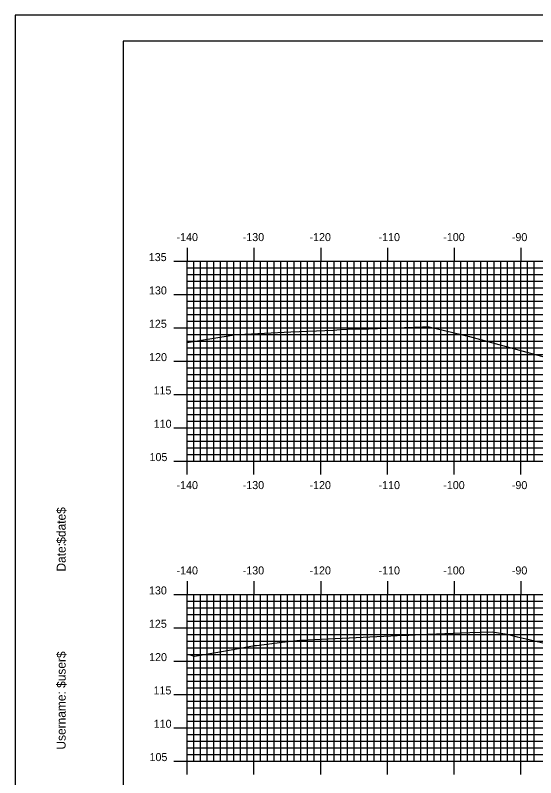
# Model space of a CAD drawing. Extents: x 854287 to 854631, y 366605 to 366825.
# Drawn here: x 854287.3 to 854365.3, y 366710.6 to 366824.9 of the extents above; entities that cross this region are included whole.
import ezdxf

# ---------------------------------------------------------------- set-up
doc = ezdxf.new("R2010")
doc.units = 0
for name, color, linetype in [('BORDER', 7, 'Continuous'), ('H_V ANNOTATION', 7, 'Continuous'), ('M_Roadway_Centerline', 7, 'Continuous'), ('MAJOR', 7, 'Continuous'), ('MINOR', 7, 'Continuous'), ('PLOT BOUNDARY', 7, 'Continuous'), ('S_Roadway_Centerline', 7, 'Continuous')]:
    doc.layers.add(name, color=color, linetype=linetype)

msp = doc.modelspace()

# ---------------------------------------------------------------- linework, layer by layer
at = {"layer": 'BORDER'}
msp.add_lwpolyline([(854303.44, 366611.06), (854623.44, 366611.06), (854623.44, 366821.06), (854303.44, 366821.06)], close=True, dxfattribs=at)
at = {"layer": 'MAJOR'}
for p, q in [((854313.04, 366790.06), (854313.04, 366788.06)), ((854323.04, 366790.06), (854323.04, 366788.06)), ((854333.04, 366790.06), (854333.04, 366788.06)), ((854343.04, 366790.06), (854343.04, 366788.06)), ((854353.04, 366790.06), (854353.04, 366788.06)), ((854363.04, 366790.06), (854363.04, 366788.06)), ((854311.04, 366788.06), (854313.04, 366788.06)), ((854313.04, 366788.06), (854593.04, 366788.06)), ((854313.04, 366758.06), (854313.04, 366788.06)), ((854313.04, 366758.06), (854313.04, 366788.06)), ((854313.04, 366788.06), (854593.04, 366788.06)), ((854323.04, 366758.06), (854323.04, 366788.06)), ((854333.04, 366758.06), (854333.04, 366788.06)), ((854343.04, 366758.06), (854343.04, 366788.06)), ((854353.04, 366758.06), (854353.04, 366788.06)), ((854363.04, 366758.06), (854363.04, 366788.06)), ((854311.04, 366783.06), (854313.04, 366783.06)), ((854313.04, 366783.06), (854593.04, 366783.06)), ((854311.04, 366778.06), (854313.04, 366778.06)), ((854313.04, 366778.06), (854593.04, 366778.06)), ((854311.04, 366773.06), (854313.04, 366773.06)), ((854313.04, 366773.06), (854593.04, 366773.06)), ((854311.04, 366768.06), (854313.04, 366768.06)), ((854313.04, 366768.06), (854593.04, 366768.06)), ((854311.04, 366763.06), (854313.04, 366763.06)), ((854313.04, 366763.06), (854593.04, 366763.06)), ((854311.04, 366758.06), (854313.04, 366758.06)), ((854313.04, 366758.06), (854593.04, 366758.06)), ((854313.04, 366758.06), (854593.04, 366758.06)), ((854313.04, 366756.05), (854313.04, 366758.06)), ((854323.04, 366756.05), (854323.04, 366758.06)), ((854333.04, 366756.05), (854333.04, 366758.06)), ((854343.04, 366756.05), (854343.04, 366758.06)), ((854353.04, 366756.05), (854353.04, 366758.06)), ((854363.04, 366756.05), (854363.04, 366758.06)), ((854313.04, 366740.06), (854313.04, 366738.06)), ((854323.04, 366740.06), (854323.04, 366738.06)), ((854333.04, 366740.06), (854333.04, 366738.06)), ((854343.04, 366740.06), (854343.04, 366738.06)), ((854353.04, 366740.06), (854353.04, 366738.06)), ((854363.04, 366740.06), (854363.04, 366738.06)), ((854311.04, 366738.06), (854313.04, 366738.06)), ((854313.04, 366738.06), (854593.04, 366738.06)), ((854313.04, 366713.06), (854313.04, 366738.06)), ((854313.04, 366713.06), (854313.04, 366738.06)), ((854313.04, 366738.06), (854593.04, 366738.06)), ((854323.04, 366713.06), (854323.04, 366738.06)), ((854333.04, 366713.06), (854333.04, 366738.06)), ((854343.04, 366713.06), (854343.04, 366738.06)), ((854353.04, 366713.06), (854353.04, 366738.06)), ((854363.04, 366713.06), (854363.04, 366738.06)), ((854311.04, 366733.06), (854313.04, 366733.06)), ((854313.04, 366733.06), (854593.04, 366733.06)), ((854311.04, 366728.06), (854313.04, 366728.06)), ((854313.04, 366728.06), (854593.04, 366728.06)), ((854311.04, 366723.06), (854313.04, 366723.06)), ((854313.04, 366723.06), (854593.04, 366723.06)), ((854311.04, 366718.06), (854313.04, 366718.06)), ((854313.04, 366718.06), (854593.04, 366718.06)), ((854311.04, 366713.06), (854313.04, 366713.06)), ((854313.04, 366713.06), (854593.04, 366713.06)), ((854313.04, 366713.06), (854593.04, 366713.06)), ((854313.04, 366711.05), (854313.04, 366713.06)), ((854323.04, 366711.05), (854323.04, 366713.06)), ((854333.04, 366711.05), (854333.04, 366713.06)), ((854343.04, 366711.05), (854343.04, 366713.06)), ((854353.04, 366711.05), (854353.04, 366713.06)), ((854363.04, 366711.05), (854363.04, 366713.06))]:
    msp.add_line(p, q, dxfattribs=at)
at = {"layer": 'MINOR'}
for p, q in [((854314.04, 366758.06), (854314.04, 366788.06)), ((854315.04, 366758.06), (854315.04, 366788.06)), ((854316.04, 366758.06), (854316.04, 366788.06)), ((854317.04, 366758.06), (854317.04, 366788.06)), ((854318.04, 366758.06), (854318.04, 366788.06)), ((854319.04, 366758.06), (854319.04, 366788.06)), ((854320.04, 366758.06), (854320.04, 366788.06)), ((854321.04, 366758.06), (854321.04, 366788.06)), ((854322.04, 366758.06), (854322.04, 366788.06)), ((854324.04, 366758.06), (854324.04, 366788.06)), ((854325.04, 366758.06), (854325.04, 366788.06)), ((854326.04, 366758.06), (854326.04, 366788.06)), ((854327.04, 366758.06), (854327.04, 366788.06)), ((854328.04, 366758.06), (854328.04, 366788.06)), ((854329.04, 366758.06), (854329.04, 366788.06)), ((854330.04, 366758.06), (854330.04, 366788.06)), ((854331.04, 366758.06), (854331.04, 366788.06)), ((854332.04, 366758.06), (854332.04, 366788.06)), ((854334.04, 366758.06), (854334.04, 366788.06)), ((854335.04, 366758.06), (854335.04, 366788.06)), ((854336.04, 366758.06), (854336.04, 366788.06)), ((854337.04, 366758.06), (854337.04, 366788.06)), ((854338.04, 366758.06), (854338.04, 366788.06)), ((854339.04, 366758.06), (854339.04, 366788.06)), ((854340.04, 366758.06), (854340.04, 366788.06)), ((854341.04, 366758.06), (854341.04, 366788.06)), ((854342.04, 366758.06), (854342.04, 366788.06)), ((854344.04, 366758.06), (854344.04, 366788.06)), ((854345.04, 366758.06), (854345.04, 366788.06)), ((854346.04, 366758.06), (854346.04, 366788.06)), ((854347.04, 366758.06), (854347.04, 366788.06)), ((854348.04, 366758.06), (854348.04, 366788.06)), ((854349.04, 366758.06), (854349.04, 366788.06)), ((854350.04, 366758.06), (854350.04, 366788.06)), ((854351.04, 366758.06), (854351.04, 366788.06)), ((854352.04, 366758.06), (854352.04, 366788.06)), ((854354.04, 366758.06), (854354.04, 366788.06)), ((854355.04, 366758.06), (854355.04, 366788.06)), ((854356.04, 366758.06), (854356.04, 366788.06)), ((854357.04, 366758.06), (854357.04, 366788.06)), ((854358.04, 366758.06), (854358.04, 366788.06)), ((854359.04, 366758.06), (854359.04, 366788.06)), ((854360.04, 366758.06), (854360.04, 366788.06)), ((854361.04, 366758.06), (854361.04, 366788.06)), ((854362.04, 366758.06), (854362.04, 366788.06)), ((854364.04, 366758.06), (854364.04, 366788.06)), ((854365.04, 366758.06), (854365.04, 366788.06)), ((854313.04, 366787.06), (854593.04, 366787.06)), ((854313.04, 366787.06), (854315.05, 366787.06)), ((854313.04, 366786.06), (854593.04, 366786.06)), ((854313.04, 366786.06), (854315.05, 366786.06)), ((854313.04, 366785.06), (854593.04, 366785.06)), ((854313.04, 366785.06), (854315.05, 366785.06)), ((854313.04, 366784.06), (854593.04, 366784.06)), ((854313.04, 366784.06), (854315.05, 366784.06)), ((854313.04, 366782.06), (854593.04, 366782.06)), ((854313.04, 366782.06), (854315.05, 366782.06)), ((854313.04, 366781.06), (854593.04, 366781.06)), ((854313.04, 366781.06), (854315.05, 366781.06)), ((854313.04, 366780.06), (854593.04, 366780.06)), ((854313.04, 366780.06), (854315.05, 366780.06)), ((854313.04, 366779.06), (854593.04, 366779.06)), ((854313.04, 366779.06), (854315.05, 366779.06)), ((854313.04, 366777.06), (854593.04, 366777.06)), ((854313.04, 366777.06), (854315.05, 366777.06)), ((854313.04, 366776.06), (854593.04, 366776.06)), ((854313.04, 366776.06), (854315.05, 366776.06)), ((854313.04, 366775.06), (854593.04, 366775.06)), ((854313.04, 366775.06), (854315.05, 366775.06)), ((854313.04, 366774.06), (854593.04, 366774.06)), ((854313.04, 366774.06), (854315.05, 366774.06)), ((854313.04, 366772.06), (854593.04, 366772.06)), ((854313.04, 366772.06), (854315.05, 366772.06)), ((854313.04, 366771.06), (854593.04, 366771.06)), ((854313.04, 366771.06), (854315.05, 366771.06)), ((854313.04, 366770.06), (854593.04, 366770.06)), ((854313.04, 366770.06), (854315.05, 366770.06)), ((854313.04, 366769.06), (854593.04, 366769.06)), ((854313.04, 366769.06), (854315.05, 366769.06)), ((854313.04, 366767.06), (854593.04, 366767.06)), ((854313.04, 366767.06), (854315.05, 366767.06)), ((854313.04, 366766.06), (854593.04, 366766.06)), ((854313.04, 366766.06), (854315.05, 366766.06)), ((854313.04, 366765.06), (854593.04, 366765.06)), ((854313.04, 366765.06), (854315.05, 366765.06)), ((854313.04, 366764.06), (854593.04, 366764.06)), ((854313.04, 366764.06), (854315.05, 366764.06)), ((854313.04, 366762.06), (854593.04, 366762.06)), ((854313.04, 366762.06), (854315.05, 366762.06)), ((854313.04, 366761.06), (854593.04, 366761.06)), ((854313.04, 366761.06), (854315.05, 366761.06)), ((854313.04, 366760.06), (854593.04, 366760.06)), ((854313.04, 366760.06), (854315.05, 366760.06)), ((854313.04, 366759.06), (854593.04, 366759.06)), ((854313.04, 366759.06), (854315.05, 366759.06)), ((854313.04, 366737.06), (854593.04, 366737.06)), ((854313.04, 366737.06), (854315.05, 366737.06)), ((854314.04, 366713.06), (854314.04, 366738.06)), ((854315.04, 366713.06), (854315.04, 366738.06)), ((854316.04, 366713.06), (854316.04, 366738.06)), ((854317.04, 366713.06), (854317.04, 366738.06)), ((854318.04, 366713.06), (854318.04, 366738.06)), ((854319.04, 366713.06), (854319.04, 366738.06)), ((854320.04, 366713.06), (854320.04, 366738.06)), ((854321.04, 366713.06), (854321.04, 366738.06)), ((854322.04, 366713.06), (854322.04, 366738.06)), ((854324.04, 366713.06), (854324.04, 366738.06)), ((854325.04, 366713.06), (854325.04, 366738.06)), ((854326.04, 366713.06), (854326.04, 366738.06)), ((854327.04, 366713.06), (854327.04, 366738.06)), ((854328.04, 366713.06), (854328.04, 366738.06)), ((854329.04, 366713.06), (854329.04, 366738.06)), ((854330.04, 366713.06), (854330.04, 366738.06)), ((854331.04, 366713.06), (854331.04, 366738.06)), ((854332.04, 366713.06), (854332.04, 366738.06)), ((854334.04, 366713.06), (854334.04, 366738.06)), ((854335.04, 366713.06), (854335.04, 366738.06)), ((854336.04, 366713.06), (854336.04, 366738.06)), ((854337.04, 366713.06), (854337.04, 366738.06)), ((854338.04, 366713.06), (854338.04, 366738.06)), ((854339.04, 366713.06), (854339.04, 366738.06)), ((854340.04, 366713.06), (854340.04, 366738.06)), ((854341.04, 366713.06), (854341.04, 366738.06)), ((854342.04, 366713.06), (854342.04, 366738.06)), ((854344.04, 366713.06), (854344.04, 366738.06)), ((854345.04, 366713.06), (854345.04, 366738.06)), ((854346.04, 366713.06), (854346.04, 366738.06)), ((854347.04, 366713.06), (854347.04, 366738.06)), ((854348.04, 366713.06), (854348.04, 366738.06)), ((854349.04, 366713.06), (854349.04, 366738.06)), ((854350.04, 366713.06), (854350.04, 366738.06)), ((854351.04, 366713.06), (854351.04, 366738.06)), ((854352.04, 366713.06), (854352.04, 366738.06)), ((854354.04, 366713.06), (854354.04, 366738.06)), ((854355.04, 366713.06), (854355.04, 366738.06)), ((854356.04, 366713.06), (854356.04, 366738.06)), ((854357.04, 366713.06), (854357.04, 366738.06)), ((854358.04, 366713.06), (854358.04, 366738.06)), ((854359.04, 366713.06), (854359.04, 366738.06)), ((854360.04, 366713.06), (854360.04, 366738.06)), ((854361.04, 366713.06), (854361.04, 366738.06)), ((854362.04, 366713.06), (854362.04, 366738.06)), ((854364.04, 366713.06), (854364.04, 366738.06)), ((854365.04, 366713.06), (854365.04, 366738.06)), ((854313.04, 366736.06), (854593.04, 366736.06)), ((854313.04, 366736.06), (854315.05, 366736.06)), ((854313.04, 366735.06), (854593.04, 366735.06)), ((854313.04, 366735.06), (854315.05, 366735.06)), ((854313.04, 366734.06), (854593.04, 366734.06)), ((854313.04, 366734.06), (854315.05, 366734.06)), ((854313.04, 366732.06), (854593.04, 366732.06)), ((854313.04, 366732.06), (854315.05, 366732.06)), ((854313.04, 366731.06), (854593.04, 366731.06)), ((854313.04, 366731.06), (854315.05, 366731.06)), ((854313.04, 366730.06), (854593.04, 366730.06)), ((854313.04, 366730.06), (854315.05, 366730.06)), ((854313.04, 366729.06), (854593.04, 366729.06)), ((854313.04, 366729.06), (854315.05, 366729.06)), ((854313.04, 366727.06), (854593.04, 366727.06)), ((854313.04, 366727.06), (854315.05, 366727.06)), ((854313.04, 366726.06), (854593.04, 366726.06)), ((854313.04, 366726.06), (854315.05, 366726.06)), ((854313.04, 366725.06), (854593.04, 366725.06)), ((854313.04, 366725.06), (854315.05, 366725.06)), ((854313.04, 366724.06), (854593.04, 366724.06)), ((854313.04, 366724.06), (854315.05, 366724.06)), ((854313.04, 366722.06), (854593.04, 366722.06)), ((854313.04, 366722.06), (854315.05, 366722.06)), ((854313.04, 366721.06), (854593.04, 366721.06)), ((854313.04, 366721.06), (854315.05, 366721.06)), ((854313.04, 366720.06), (854593.04, 366720.06)), ((854313.04, 366720.06), (854315.05, 366720.06)), ((854313.04, 366719.06), (854593.04, 366719.06)), ((854313.04, 366719.06), (854315.05, 366719.06)), ((854313.04, 366717.06), (854593.04, 366717.06)), ((854313.04, 366717.06), (854315.05, 366717.06)), ((854313.04, 366716.06), (854593.04, 366716.06)), ((854313.04, 366716.06), (854315.05, 366716.06)), ((854313.04, 366715.06), (854593.04, 366715.06)), ((854313.04, 366715.06), (854315.05, 366715.06)), ((854313.04, 366714.06), (854593.04, 366714.06)), ((854313.04, 366714.06), (854315.05, 366714.06))]:
    msp.add_line(p, q, dxfattribs=at)
at = {"layer": 'PLOT BOUNDARY'}
msp.add_lwpolyline([(854287.26, 366604.94), (854627.26, 366604.94), (854627.26, 366824.94), (854287.26, 366824.94)], close=True, dxfattribs=at)
at = {"layer": 'S_Roadway_Centerline'}
for points in [[(854313.04, 366775.84), (854319.47, 366776.91), (854320.36, 366777.06), (854320.65, 366777.07), (854328.56, 366777.43), (854334.98, 366777.72), (854335.94, 366777.81), (854338.24, 366777.9), (854340.21, 366777.91), (854348.32, 366778.22), (854349.29, 366778.22), (854355.35, 366776.74), (854369.43, 366772.89)], [(854313.04, 366729.12), (854314.16, 366728.81), (854314.41, 366728.84), (854319.62, 366729.76), (854323.13, 366730.38), (854323.4, 366730.42), (854327.27, 366730.88), (854329.91, 366731.18), (854330, 366731.18), (854343.55, 366731.84), (854345.49, 366731.94), (854345.55, 366731.93), (854346.24, 366731.95), (854349.13, 366732.08), (854355.37, 366732.33), (854358.76, 366732.47), (854361, 366732.11), (854362.5, 366731.71), (854364.31, 366731.31), (854374.29, 366728.86)]]:
    msp.add_lwpolyline(points, dxfattribs=at)

# ---------------------------------------------------------------- texts
at = {"layer": 'BORDER'}
for s, p in [('$date$', (854294.81, 366745.67)), ('Date:', (854294.81, 366741.49)), ('$user$', (854294.81, 366724.04)), ('Username:', (854294.81, 366714.79))]:
    msp.add_text(s, height=1.339, rotation=90, dxfattribs=at).set_placement(p)
at = {"layer": 'H_V ANNOTATION'}
for s, p in [('-140', (854311.43, 366791.06)), ('-130', (854321.35, 366791.06)), ('-120', (854331.36, 366791.06)), ('-110', (854341.71, 366791.06)), ('-100', (854351.41, 366791.06)), ('-90', (854361.69, 366791.06)), ('135', (854307.27, 366788.06)), ('130', (854307.3, 366783.06)), ('125', (854307.29, 366778.06)), ('120', (854307.32, 366773.06)), ('115', (854307.98, 366768.06)), ('110', (854308.01, 366763.06)), ('105', (854307.38, 366758.06)), ('-140', (854311.43, 366753.86)), ('-130', (854321.35, 366753.86)), ('-120', (854331.36, 366753.86)), ('-110', (854341.71, 366753.86)), ('-100', (854351.41, 366753.86)), ('-90', (854361.69, 366753.86)), ('-140', (854311.43, 366741.06)), ('-130', (854321.35, 366741.06)), ('-120', (854331.36, 366741.06)), ('-110', (854341.71, 366741.06)), ('-100', (854351.41, 366741.06)), ('-90', (854361.69, 366741.06)), ('130', (854307.3, 366738.06)), ('125', (854307.29, 366733.06)), ('120', (854307.32, 366728.06)), ('115', (854307.98, 366723.06)), ('110', (854308.01, 366718.06)), ('105', (854307.38, 366713.06))]:
    msp.add_text(s, height=1.2, dxfattribs=at).set_placement(p)
at = {"layer": 'M_Roadway_Centerline'}
for s, p in [('C', (854335.94, 366777.81)), ('L', (854335.94, 366777.8)), ('C', (854345.49, 366731.94)), ('L', (854345.49, 366731.93))]:
    msp.add_text(s, height=0.0146, dxfattribs=at).set_placement(p)
at = {"layer": 'MAJOR'}
for p in [(854313.03, 366758.06), (854313.03, 366713.06)]:
    msp.add_text('-', height=0.012, dxfattribs=at).set_placement(p)

doc.saveas('drawing.dxf')
